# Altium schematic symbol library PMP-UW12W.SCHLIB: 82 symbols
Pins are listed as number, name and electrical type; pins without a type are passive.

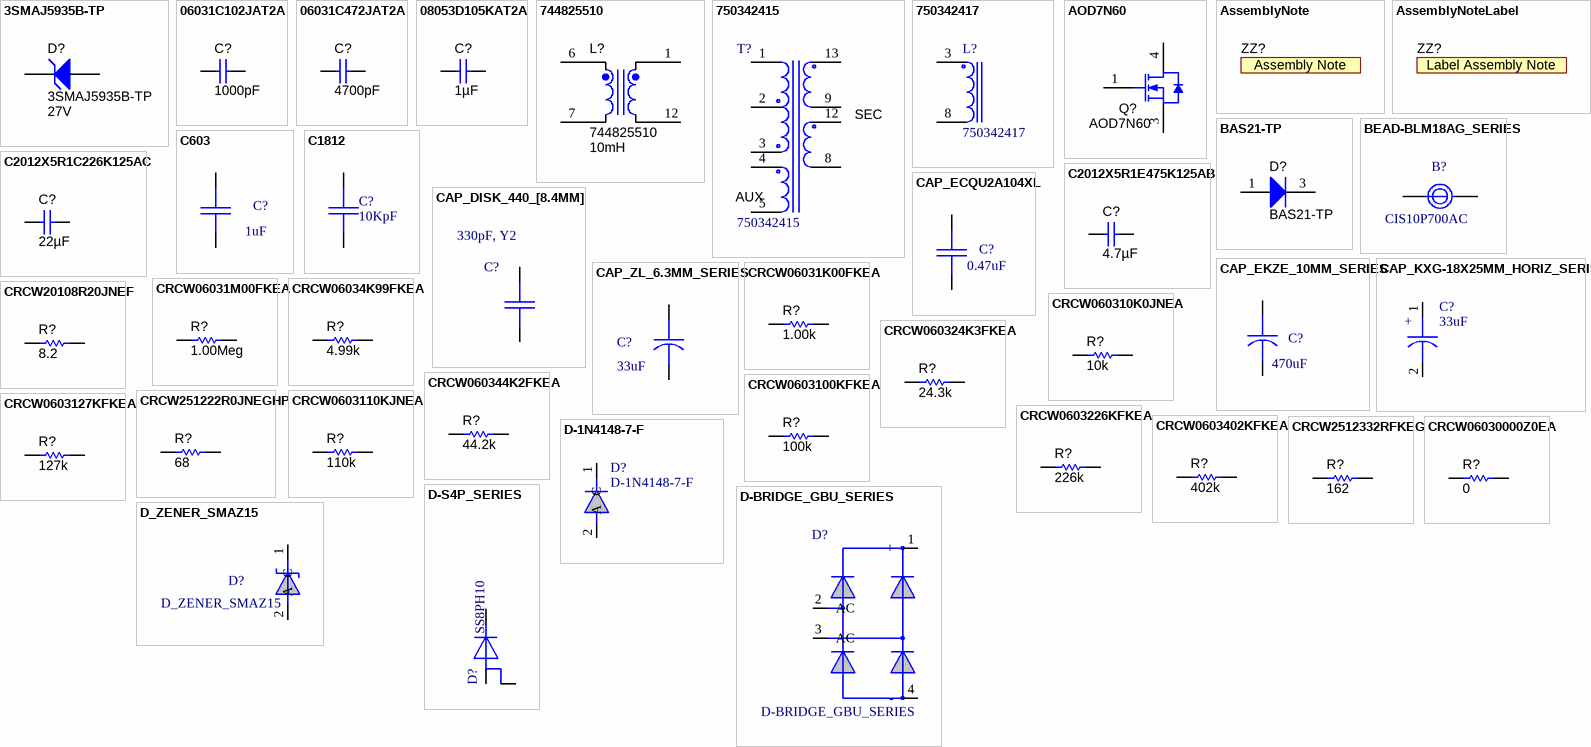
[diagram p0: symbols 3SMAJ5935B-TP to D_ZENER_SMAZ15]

## 3SMAJ5935B-TP
designator D?  value 27V
Diode, Zener, 27V, 3W, SMA; Manufacturer: Micro Commercial Components; SymbolCreator: a0412235; U/M: EA; Power_W: 3; Vz_V: 27; RJA_CperW: 226
signal-integrity model Diode
footprint SMA
pins: 1 K, 2 A

## 06031C102JAT2A
designator C?  ValueDisplayed: 1000pF  (hidden comment: 06031C102JAT2A)
CAP, CERM, 1000pF, 100V, +/-5%, X7R, 0603; Manufacturer: AVX; Polarized: N; CompType: Capacitor; U/M: EA; Cap_F: 0.000000001; Tolerance_%: 5; ESR_Ohm: 0.276; Value1: 0.276 ohm; VDC_V: 100; TaMin_C: -55; TaMax_C: 125; Cap_Case: 0603
signal-integrity model Cap
simulation model Cap
footprint 0603
footprint 0603M
footprint 0603L
footprint 0603_HV
footprint 0603S
pins: 1, 2

## 06031C472JAT2A
designator C?  ValueDisplayed: 4700pF  (hidden comment: 06031C472JAT2A)
CAP, CERM, 4700pF, 100V, +/-5%, X7R, 0603; Manufacturer: AVX; Polarized: N; CompType: Capacitor; U/M: EA; Cap_F: 0.0000000047; Tolerance_%: 5; ESR_Ohm: 0.136; Value1: 0.136 ohm; VDC_V: 100; TaMin_C: -55; TaMax_C: 125; Cap_Case: 0603
signal-integrity model Cap
simulation model Cap
footprint 0603
footprint 0603M
footprint 0603L
footprint 0603_HV
footprint 0603S
pins: 1, 2

## 08053D105KAT2A
designator C?  ValueDisplayed: 1µF  (hidden comment: 08053D105KAT2A)
CAP, CERM, 1uF, 25V, +/-10%, X5R, 0805; Manufacturer: AVX; Polarized: N; CompType: Capacitor; U/M: EA; Cap_F: 0.000001; Tolerance_%: 10; ESR_Ohm: 0.012; Value1: 0.012 ohm; VDC_V: 25; TaMin_C: -55; TaMax_C: 85; Cap_Case: 0805
signal-integrity model Cap
simulation model Cap
footprint 0805_HV
footprint 0805
footprint 0805M
footprint 0805L
pins: 1, 2

## 744825510
designator L?  ValueDisplayed: 10mH
Coupled inductor, 10mH, 5A, 0.055 ohm, TH; Manufacturer: Wurth Elektronik eiSos; SymbolCreator: a0799628; Ind_H: 10.0E-3; DCR_ohm: 0.055; Isat: 5
footprint WE-CMB_XL
pins: 1, 6, 7, 12

## 750342415
designator T?
TRANSFOERMER, 856uH, +/-10%, TH, 14-PIN; Manufacturer: WURTH ELEKTRONIK; CompType: TRANSFORMER; SymbolCreator: x0199378
footprint WE_750342415 (TRANSFOERMER, TH)
pins: 1, 2, 3, 4, 5, 8, 9, 12, 13

## 750342417
designator L?
TRANSFOERMER, 300uH, +/-10%, TH, 10-PIN; Manufacturer: WURTH ELEKTRONIK; CompType: TRANSFORMER; SymbolCreator: x0199378
footprint WE_750342417 (TRANSFOERMER, TH)
pins: 3, 8

## AOD7N60
designator Q?
MOSFET, N-CH, 600V, 7A, DPAK; Manufacturer: AOS; Alternate Manufacturer: None; U/M: EA; ChType: N; VdsMax_V: 600; Value1: ? ohm; Value2: 19.3 nC; QgTyp_nC: 19.3; Vgs_V: 30; IdsMax_A: 7
footprint DPAK
pins: 1 G, 3 S, 4 D

## AssemblyNote
designator ZZ?  (no BOM)
These assemblies are ESD sensitive, ESD precautions shall be observed.; Part_Number: Part Number; SymbolCreator: codlsc; CompType: AssemblyNote
footprint AssemblyNote

## AssemblyNoteLabel
designator ZZ?  (no BOM)
This Assembly Note is for PCB labels only; Part_Number: Part Number; SymbolCreator: a0412235
footprint AssemblyNoteLabel

## BAS21-TP
designator D?
Diode, P-N, 200V, 200A, SOT-23; Manufacturer: Micro Commercial Components; U/M: EA; Vf_V: 1.25; Value2: 1.25V; Io_A: 200; TJmax_C: 150; RJC_CperW: 430
signal-integrity model Model Name (Model Description)
footprint SOT-23
footprint SOT-23M
footprint SOT-23L
pins: 1 A, 3 K

## BEAD-BLM18AG_SERIES
designator B?, comment CIS10P700AC
FERRITE CHIP 70 OHM 4000MA 0603; Manufacturer: Samsung; Second Source: C:\program files\p-cad 2004\pcad_pdf's\Bead BML SERIES.pdf; Reference: \\vette02\pmp_pcb\pcad_pdf's\Bead BML SERIES.pdf; Area: 5.87 mm; Value: 70ohm; PCB DECAL: 0603
footprint xxxx (Footprint not found)
footprint 0603 (0603 from SM-752 data)
pins: 1, 2

## C603
designator C?  value 1uF  (hidden comment: C603)
CAP CER 1UF 25V 10% X7R 0603; Manufacturer: Kemet; PartNumber: C0603C105K3RACTU; Area: 5650
footprint C603
pins: 1, 2

## C1812
designator C?, comment value 10KpF  (hidden comment: C4532CH2J103K160KA)
Corporation CAP CER 10000PF 630V 10% CH 1812; Manufacturer: TDK Corporation; Area: 43,360
footprint C1812
pins: 1, 2
1 alternate drawing of the same symbol

## C2012X5R1C226K125AC
designator C?  ValueDisplayed: 22µF  (hidden comment: C2012X5R1C226K125AC)
CAP, CERM, 22uF, 16V, +/-10%, X5R, 0805; Manufacturer: TDK; Polarized: N; CompType: Capacitor; U/M: EA; Cap_F: 0.000022; Tolerance_%: 10; Value1: Unknown; VDC_V: 16; TaMin_C: -55; TaMax_C: 85; Cap_Case: 0805
signal-integrity model Cap
simulation model Cap
footprint 0805_HV
footprint 0805
footprint 0805M
footprint 0805L
pins: 1, 2

## C2012X5R1E475K125AB
designator C?  ValueDisplayed: 4.7µF  (hidden comment: C2012X5R1E475K125AB)
CAP, CERM, 4.7uF, 25V, +/-10%, X5R, 0805; Manufacturer: TDK; Polarized: N; CompType: Capacitor; U/M: EA; Cap_F: 0.0000047; Tolerance_%: 10; Value1: Unknown; VDC_V: 25; TaMin_C: -55; TaMax_C: 85; Cap_Case: 0805
signal-integrity model Cap
simulation model Cap
footprint 0805_HV
footprint 0805
footprint 0805M
footprint 0805L
pins: 1, 2

## CAP_DISK_440_[8.4MM]
designator C?  value 330pF, Y2  (hidden comment: CAP_DISK_440_[8.4MM])
CAP CER 330PF 300VAC 10% RADIAL; Manufacturer: Vishay; Part_Number: VY2331K29Y5SS63V7; PartNumber: Part Number; Description: Capacitor, 300VAC, X1Y2, ±10%; Area: 103.50 mm; Reference: \\vette02\pmp_pcb\pcad_pdf's\440l.pdf; Second_Source: C:\program files\p-cad 2004\pcad_pdf's\ABB0000CE12.pdf; Type: CAP_DISK_720; PCB DECAL: CAP_DISK_8.4MM; Second Source: C:\program files\p-cad2004pcad_pdf's\440l.pdf
footprint CAP_DISK_8.4MM
pins: 1, 2

## CAP_ECQU2A104XL
designator C?, comment value 0.47uF  (hidden comment: R46KI347050P1M)
CAP FILM 0.47UF 560VDC RADIAL; Manufacturer: Kemet; PCB DECAL: 18.00mm x 9.00mm; Area: 97500
footprint CAP_591MIL
pins: 1, 2

## CAP_EKZE_10MM_SERIES
designator C?  value 470uF  (hidden comment: CAP_EKZE_10MM_SERIES)
CAP ALUM 470UF 35V 20% RADIAL; Manufacturer: Panasonic; Part_Number: EEU-FM1V471; Part_Number: Part Number; Area: 96.42 mm; PCB DECAL: CAP_ALUM-10MM; Second Source: C:\program files\p-cad 2004\pcad_pdf's\ekze_cap.pdf; Reference: \\vette02\pmp_pcb\pcad_pdf's\ekze_cap.pdf
footprint CAP_ALUM-10MM
pins: 1, 2

## CAP_KXG-18X25MM_HORIZ_SERIES
designator C?, comment 33uF
Capacitor, Electrolytic, -40 to +105 °C; PartNumber: EKXG451ELL330MM20S; Manufacturer: Nippon; Area: 667.40 mm; Value: xx uH
footprint CAP_EEUFC1H
pins: 1, 2
1 alternate drawing of the same symbol

## CAP_ZL_6.3MM_SERIES
designator C?  value 33uF  (hidden comment: CAP_ZL_6.3MM_SERIES)
CAP ALUM 33UF 35V 20% RADIAL; Manufacturer: Rubycon; Part_Number: 35YXJ33M5X11; PartNumber: Part Number; Area: 70,686; Type: CAP_ZL_6.3MM SERIES; PCB DECAL: CAP_ZL-6.3MM
footprint CAP_ZL-6.3MM
pins: 1, 2

## CRCW06031K00FKEA
designator R?  value 1.00k  (hidden comment: CRCW06031K00FKEA)
RES, 1.00k ohm, 1%, 0.1W, 0603; Manufacturer: Vishay-Dale; CompType: Resistor; Res_ohm: 1000; Value_Code: 1k00; Tolerance_%: 1; Power_W: 0.1; VDC_V: 75; TempCo: 100 ppm/C; EIA_Code: E96; U/M: EA
signal-integrity model Resistor
simulation model Resistor
footprint 0603
footprint 0603M
footprint 0603L
footprint 0603_HV
footprint 0603S
pins: 1, 2

## CRCW06031M00FKEA
designator R?  value 1.00Meg  (hidden comment: CRCW06031M00FKEA)
RES, 1.00Meg ohm, 1%, 0.1W, 0603; Manufacturer: Vishay-Dale; CompType: Resistor; Res_ohm: 1000000; Value_Code: 1M00; Tolerance_%: 1; Power_W: 0.1; VDC_V: 75; TempCo: 100 ppm/C; EIA_Code: E96; U/M: EA
signal-integrity model Resistor
simulation model Resistor
footprint 0603
footprint 0603M
footprint 0603L
footprint 0603_HV
footprint 0603S
pins: 1, 2

## CRCW06034K99FKEA
designator R?  value 4.99k  (hidden comment: CRCW06034K99FKEA)
RES, 4.99k ohm, 1%, 0.1W, 0603; Manufacturer: Vishay-Dale; CompType: Resistor; Res_ohm: 4990; Value_Code: 4k99; Tolerance_%: 1; Power_W: 0.1; VDC_V: 75; TempCo: 100 ppm/C; EIA_Code: E96; U/M: EA
signal-integrity model Resistor
simulation model Resistor
footprint 0603
footprint 0603M
footprint 0603L
footprint 0603_HV
footprint 0603S
pins: 1, 2

## CRCW20108R20JNEF
designator R?  value 8.2  (hidden comment: CRCW20108R20JNEF)
RES, 8.2 ohm, 5%, 0.75W, 2010; Manufacturer: Vishay-Dale; CompType: Resistor; Value_Code: 8R20; Tolerance_%: 5; Power_W: 0.75; VDC_V: 400; TempCo: 200 ppm/C; EIA_Code: E24; U/M: EA
signal-integrity model Resistor
simulation model Resistor
footprint 2010M
footprint 2010L
footprint 2010
pins: 1, 2

## CRCW060310K0JNEA
designator R?  value 10k  (hidden comment: CRCW060310K0JNEA)
RES, 10k ohm, 5%, 0.1W, 0603; Manufacturer: Vishay-Dale; CompType: Resistor; Res_ohm: 10000; Value_Code: 10k0; Tolerance_%: 5; Power_W: 0.1; VDC_V: 75; TempCo: 200 ppm/C; EIA_Code: E24; U/M: EA
signal-integrity model Resistor
simulation model Resistor
footprint 0603
footprint 0603M
footprint 0603L
footprint 0603_HV
footprint 0603S
pins: 1, 2

## CRCW060324K3FKEA
designator R?  value 24.3k  (hidden comment: CRCW060324K3FKEA)
RES, 24.3k ohm, 1%, 0.1W, 0603; Manufacturer: Vishay-Dale; CompType: Resistor; Res_ohm: 24300; Value_Code: 24k3; Tolerance_%: 1; Power_W: 0.1; VDC_V: 75; TempCo: 100 ppm/C; EIA_Code: E96; U/M: EA
signal-integrity model Resistor
simulation model Resistor
footprint 0603
footprint 0603M
footprint 0603L
footprint 0603_HV
footprint 0603S
pins: 1, 2

## CRCW060344K2FKEA
designator R?  value 44.2k  (hidden comment: CRCW060344K2FKEA)
RES, 44.2k ohm, 1%, 0.1W, 0603; Manufacturer: Vishay-Dale; CompType: Resistor; Res_ohm: 44200; Value_Code: 44k2; Tolerance_%: 1; Power_W: 0.1; VDC_V: 75; TempCo: 100 ppm/C; EIA_Code: E96; U/M: EA
signal-integrity model Resistor
simulation model Resistor
footprint 0603
footprint 0603M
footprint 0603L
footprint 0603_HV
footprint 0603S
pins: 1, 2

## CRCW251222R0JNEGHP
designator R?, comment value 68  (hidden comment: RHC2512FT68R0)
RES 68 OHM 2W 1% 2512; Manufacturer: Stackpole Electronics Inc; CompType: Resistor; Tolerance_%: 1
signal-integrity model Resistor
simulation model Resistor
footprint 2512M
footprint 2512L
footprint 2512
pins: 1, 2

## CRCW0603100KFKEA
designator R?  value 100k  (hidden comment: CRCW0603100KFKEA)
RES, 100k ohm, 1%, 0.1W, 0603; Manufacturer: Vishay-Dale; CompType: Resistor; Res_ohm: 100000; Tolerance_%: 1; Power_W: 0.1; VDC_V: 75; TempCo: 100 ppm/C; EIA_Code: E96; U/M: EA
signal-integrity model Resistor
simulation model Resistor
footprint 0603
footprint 0603M
footprint 0603L
footprint 0603_HV
footprint 0603S
pins: 1, 2

## CRCW0603110KJNEA
designator R?  value 110k  (hidden comment: CRCW0603110KJNEA)
RES, 110k ohm, 5%, 0.1W, 0603; Manufacturer: Vishay-Dale; CompType: Resistor; Res_ohm: 110000; Tolerance_%: 5; Power_W: 0.1; VDC_V: 75; TempCo: 200 ppm/C; EIA_Code: E24; U/M: EA
signal-integrity model Resistor
simulation model Resistor
footprint 0603
footprint 0603M
footprint 0603L
footprint 0603_HV
footprint 0603S
pins: 1, 2

## CRCW0603127KFKEA
designator R?  value 127k  (hidden comment: CRCW0603127KFKEA)
RES, 127k ohm, 1%, 0.1W, 0603; Manufacturer: Vishay-Dale; CompType: Resistor; Res_ohm: 127000; Tolerance_%: 1; Power_W: 0.1; VDC_V: 75; TempCo: 100 ppm/C; EIA_Code: E96; U/M: EA
signal-integrity model Resistor
simulation model Resistor
footprint 0603
footprint 0603M
footprint 0603L
footprint 0603_HV
footprint 0603S
pins: 1, 2

## CRCW0603226KFKEA
designator R?  value 226k  (hidden comment: CRCW0603226KFKEA)
RES, 226k ohm, 1%, 0.1W, 0603; Manufacturer: Vishay-Dale; CompType: Resistor; Res_ohm: 226000; Tolerance_%: 1; Power_W: 0.1; VDC_V: 75; TempCo: 100 ppm/C; EIA_Code: E96; U/M: EA
signal-integrity model Resistor
simulation model Resistor
footprint 0603
footprint 0603M
footprint 0603L
footprint 0603_HV
footprint 0603S
pins: 1, 2

## CRCW0603402KFKEA
designator R?  value 402k  (hidden comment: CRCW0603402KFKEA)
RES, 402k ohm, 1%, 0.1W, 0603; Manufacturer: Vishay-Dale; CompType: Resistor; Res_ohm: 402000; Tolerance_%: 1; Power_W: 0.1; VDC_V: 75; TempCo: 100 ppm/C; EIA_Code: E96; U/M: EA
signal-integrity model Resistor
simulation model Resistor
footprint 0603
footprint 0603M
footprint 0603L
footprint 0603_HV
footprint 0603S
pins: 1, 2

## CRCW2512332RFKEG
designator R?, comment value 162  (hidden comment: CRCW2512162RFKEGHP)
RES 162 OHM 1.5W 1% 2512 SMD; Manufacturer: Vishay-Dale; CompType: Resistor; Value_Code: 162R; Tolerance_%: 1; EIA_Code: E96; U/M: EA
signal-integrity model Resistor
simulation model Resistor
footprint 2512M
footprint 2512L
footprint 2512
pins: 1, 2

## CRCW06030000Z0EA
designator R?  value 0  (hidden comment: CRCW06030000Z0EA)
RES, 0 ohm, 5%, 0.1W, 0603; Manufacturer: Vishay-Dale; CompType: Resistor; Value_Code: 0000; Tolerance_%: 5; Power_W: 0.1; VDC_V: 75; TempCo: 200 ppm/C; EIA_Code: E24; U/M: EA
signal-integrity model Resistor
simulation model Resistor
footprint 0603
footprint 0603M
footprint 0603L
footprint 0603_HV
footprint 0603S
pins: 1, 2

## D-1N4148-7-F
designator D?
Diode, Signal, 300-mA, 75-V, 350-mW; PartNumber: 1N4148W-7-F; Manufacturer: Diodes; Area: 13300; Value: 1N4148W-7-F
footprint D_SOD123
pins: 1 C, 2 A

## D-BRIDGE_GBU_SERIES
designator D?
Diode, Bridge Rectifier, 8 A, xxxV; PartNumber: GBUxx; Manufacturer: Fairchild; Area: 163800; Value: GBUxx
footprint BRIDGE-INLINE-210-C
pins: 1 +, 2 AC, 3 AC, 4 -

## D-S4P_SERIES
designator D?  value SS8PH10  (hidden comment: D-S4P_SERIES)
Diode Schottky, 8A, 100V; PartNumber: SS8PH10-M3/86A; Manufacturer: Vishay; Area: 73600; PCB DECAL: TO-277[SMPC]; Second Source: C:\program files\p-cad 2004\pcad_pdf's\s4pm[1].pdf; Reference: \\vette02\pmp_pcb\pcad_pdf's\s4pm[1].pdf
footprint TO-277[SMPC]
pins: 1, 2 A, 3 C

## D_ZENER_SMAZ15
designator D?
Diode, Zener,15-V, 1W; PartNumber: SMAZ15; Manufacturer: Diodes; Area: 37520; Value: SMAZ15
footprint DIODE_SMA
pins: 1 C, 2 A

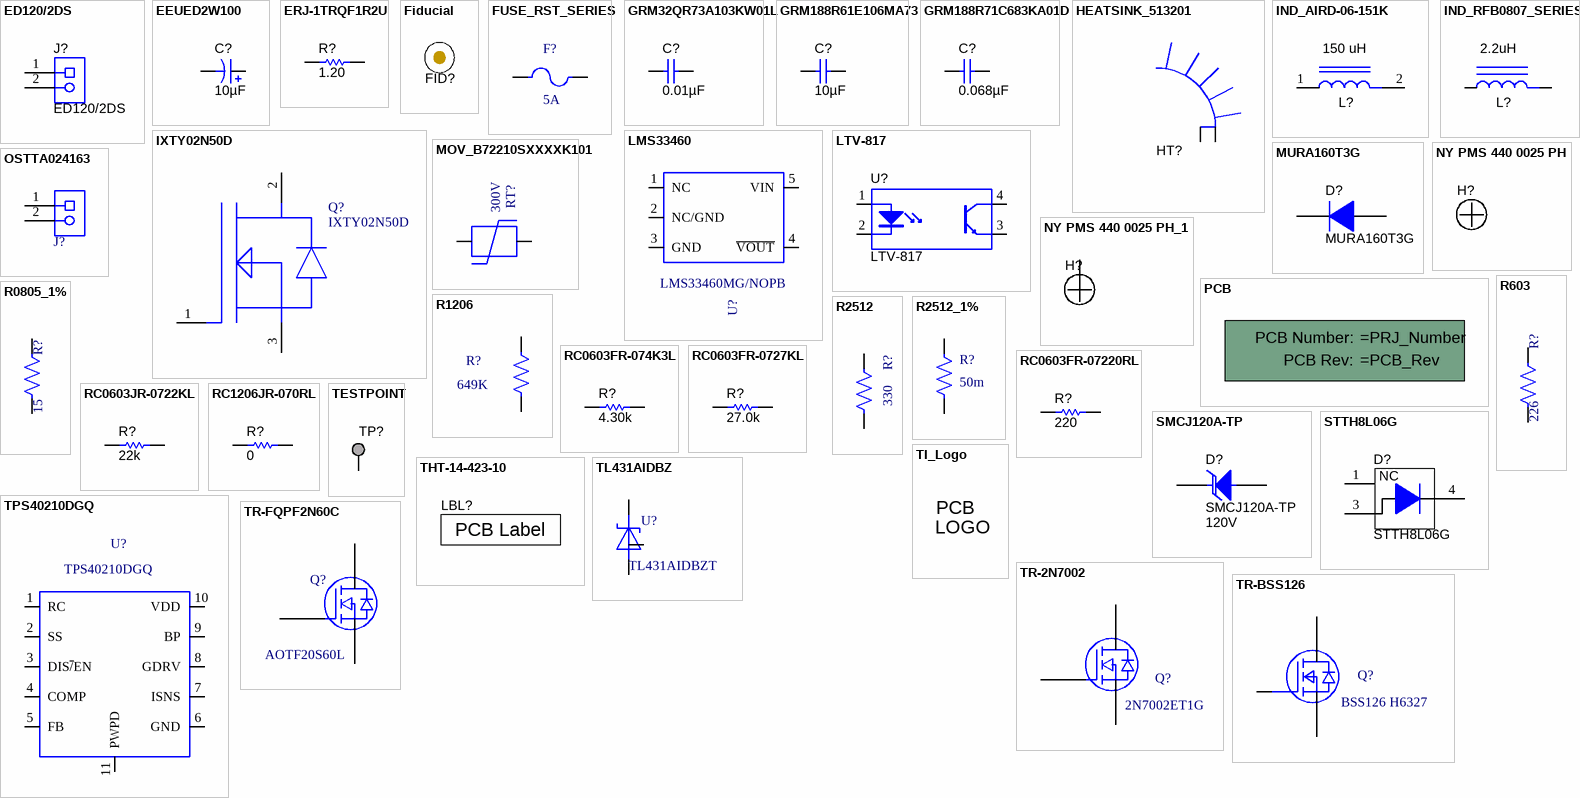
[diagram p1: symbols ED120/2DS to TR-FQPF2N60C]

## ED120/2DS
designator J?
TERMINAL BLOCK 5.08MM VERT 2POS, TH; Manufacturer: On-Shore Technology; SymbolCreator: a0412235; U/M: EA
footprint CONN_ED120-2DS
pins: 1, 2

## EEUED2W100
designator C?  ValueDisplayed: 10µF  (hidden comment: EEUED2W100)
CAP, AL, 10uF, 450V, +/-20%, 2.864788 ohm, TH; Manufacturer: Panasonic; Polarized: Y; CompType: Capacitor; U/M: EA; Cap_F: 0.00001; Tolerance_%: 20; VDC_V: 450; IRMS_A: 0.35; TaMin_C: -25; TaMax_C: 105; AC_Derating: 0.3
signal-integrity model Cap
simulation model Cap
footprint CAPPR5-12.5X20
footprint CAPPR5-12.5X20_HorizontalUp
footprint CAPPR5-12.5X20_HorizontalDown
pins: 1 +, 2 -

## ERJ-1TRQF1R2U
designator R?  value 1.20  (hidden comment: ERJ-1TRQF1R2U)
RES, 1.20 ohm, 1%, 1W, 2512; Manufacturer: Panasonic; CompType: Resistor; Res_ohm: 1.2; Value_Code: 1R20; Tolerance_%: 1; TempCo: 100 ppm/C; U/M: EA
signal-integrity model Resistor
simulation model Resistor
footprint 2512M
footprint 2512L
footprint 2512
pins: 1, 2

## Fiducial
designator FID?  (value not drawn)
Fiducial mark.  There is nothing to buy or mount.; Part_Number: Part Number; SymbolCreator: codlsc
footprint Fiducial10-30
footprint Fiducial10-20
footprint Fiducial15-30
footprint Fiducial20-40
footprint Fiducial6.4-20
footprint Fiducial10-30_Panel

## FUSE_RST_SERIES
designator F?  value 5A  (hidden comment: FUSE_RST_SERIES)
FUSE SLOW 250VAC 5A RADIAL; Manufacturer: BEL; PartNumber: RST 5; Area: 43.2 mm; PCB DECAL: FUSE_4X8.5-5.08P; Reference: \\vette02\pmp_pcb\pcad_pdf's\RST.pdf; Second Source: C:\program files\p-cad 2004\pcad_pdf's\RST.pdf
footprint FUSE_4X8.5-5.08P
pins: 1, 2

## GRM32QR73A103KW01L
designator C?  ValueDisplayed: 0.01µF  (hidden comment: GRM32QR73A103KW01L)
CAP, CERM, 0.01uF, 1000V, +/-10%, X7R, 1210; Manufacturer: MuRata; Polarized: N; CompType: Capacitor; U/M: EA; Cap_F: 0.00000001; Tolerance_%: 10; Value1: Unknown; VDC_V: 1000; TaMin_C: -55; TaMax_C: 125; Cap_Case: 1210
signal-integrity model Cap
simulation model Cap
footprint 1210
footprint 1210M
footprint 1210L
pins: 1, 2

## GRM188R61E106MA73
designator C?  ValueDisplayed: 10µF  (hidden comment: GRM188R61E106MA73)
CAP, CERM, 10uF, 25V, +/-20%, X5R, 0603; Manufacturer: MuRata; Polarized: N; CompType: Capacitor; U/M: EA; Cap_F: 0.00001; Tolerance_%: 20; Value1: Unknown; VDC_V: 25; TaMin_C: -55; TaMax_C: 85; Cap_Case: 0603
signal-integrity model Cap
simulation model Cap
footprint 0603
footprint 0603M
footprint 0603L
footprint 0603_HV
footprint 0603S
pins: 1, 2

## GRM188R71C683KA01D
designator C?  ValueDisplayed: 0.068µF  (hidden comment: GRM188R71C683KA01D)
CAP, CERM, 0.068uF, 16V, +/-10%, X7R, 0603; Manufacturer: MuRata; Polarized: N; CompType: Capacitor; U/M: EA; Cap_F: 0.000000068; Tolerance_%: 10; Value1: Unknown; VDC_V: 16; TaMin_C: -55; TaMax_C: 125; Cap_Case: 0603
signal-integrity model Cap
simulation model Cap
footprint 0603
footprint 0603M
footprint 0603L
footprint 0603_HV
footprint 0603S
pins: 1, 2

## HEATSINK_513201
designator HT?, comment HEATSINK_513102B02500G  (value not drawn)
HEATSINK TO-220 W/PINS 1.5"TALL; Manufacturer: Aavid Thermalloy; area: 739800
footprint HEATSINK_513201
pins: 1, 2

## IND_AIRD-06-151K
designator L?, comment 150 uH
INDUCTOR 150UH 4.0A 10%; Manufacturer: Abracon Corporation; Part Number: AIRD-06-151K; Area: 113411; sp: AIRD-06-151K-ND; sup: Digi-Key
footprint IND_AIRD-06-151K
pins: 1, 2

## IND_RFB0807_SERIES
designator L?, comment 2.2uH
INDUCTOR 2.2UH 4.1A RADIAL; Manufacturer: Taiyo Yuden; Part_Number: LHL08TB2R2M; Area: 113411; Type: PD2 744; PCB DECAL: IND_200_MIL
footprint IND_200_MIL
pins: 1, 2

## IXTY02N50D
designator Q?
DISCRETE, MOSFET N-CH 500V 200MA, DPAK; Manufacturer: IXYS; SymbolCreator: x0199378
footprint TO228P991X238-3N
pins: 1 G, 2 D, 3 S

## LMS33460
designator U?  value LMS33460MG/NOPB  (hidden comment: LMS33460)
IC DETECTOR UNDER VOLT 3V SC70-5; Manufacturer: TI; Second Source: C:\program files\p-cad 2004\pcad_pdf's\lms33460[1].pdf; Reference: \\vette02\pmp_pcb\pcad_pdf's\lms33460[1].pdf; Area: 12.05 mm; PCB DECAL: SC-70-5
footprint SC-70-5
pins: 1 NC, 2 NC/GND, 3 GND, 4 ~{VOUT}, 5 VIN

## LTV-817
designator U?
Opto-Isolator, 1 Channel, TH; Manufacturer: Lite-On; CompType: OPTOCOUPLER; U/M: EA
footprint DIP762W60P254L460H350Q4B
pins: 1 A, 2 K, 3 E, 4 C

## MOV_B72210SXXXXK101
designator RT?  value 300V  (hidden comment: MOV_B72210SXXXXK101)
MOV, 300V; Manufacturer: Bourns; Part_Number: MOV-10D471KTR; Area: 85,500; PCB DECAL: DISK-472
footprint DISK-472
pins: 1, 2

## MURA160T3G
designator D?
Diode, Ultrafast, 600V, 1A, SMA; Manufacturer: ON Semiconductor; U/M: EA; Vf_V: 1.05; Value2: 1.05V; Io_A: 1; Vr_V: 600; TJmax_C: 175
signal-integrity model Diode
simulation model Dmura160t3
footprint SMA
pins: 1 K, 2 A

## NY PMS 440 0025 PH
designator H?
Mounting Hole M3 3.5mm; Manufacturer: STD; CompType: Hardware; U/M: EA
footprint MH3.2_H5_W6_KO8_STARHEAD

## NY PMS 440 0025 PH_1
designator H?
Mounting Hole M3 3.5mm; Manufacturer: STD; CompType: Hardware; U/M: EA
footprint NY PMS 440 0025 PH (4-40 nylon screw and mounting hole)
footprint NY PMS 440 0025 PH (4-40 nylon screw and mounting hole)
pins: 1

## OSTTA024163
designator J?  (value not drawn)
Terminal Block, 2x1, 5.08mm, TH; PartNumber: OSTTC022162; Manufacturer: On-Shore Technology; SymbolCreator: a0412235; U/M: EA
footprint On-Shore_OSTTA024163
pins: 1, 2

## PCB
designator !PCB?  (mechanical)
Printed Circuit Board; Manufacturer: Any; Part_Number: Part Number; SymbolCreator: a0412235; CompType: PCB
1 alternate drawing of the same symbol

## R603
designator R?  value 226  (hidden comment: R603)
RES 226 OHM 1/10W 1% 0603 SMD; Part_Number: RC0603FR-07226RL; Manufacturer: Yageo; Area: 5650
footprint R603
pins: 1, 2

## R0805_1%
designator R?  value 15  (hidden comment: R0805_1%)
RES 15.0 OHM 1/8W 1% 0805 SMD; Part_Number: RC0805FR-0715RL; Manufacturer: Yageo; Area: 15,300; PCB DECAL: R0805
footprint R0805
pins: 1, 2

## R1206
designator R?  value 649K  (hidden comment: R1206)
RES 649K OHM 1/4W 1% 1206 SMD; Manufacturer: Yageo; PartNumber: RC1206FR-07649KL; Area: 15390
footprint r1206
pins: 1, 2

## R2512
designator R?  value 330  (hidden comment: R2512)
RES 330 OHM 1W 5% 2512; Manufacturer: Samsung; PartNumber: RC6432J331CS; Area: 35100
footprint R2512
pins: 1, 2

## R2512_1%
designator R?  value 50m  (hidden comment: R2512_1%)
RES 0.05 OHM 1W 1% 2512 SMD; Part_Number: LRMAM2512-R05FT4; Manufacturer: TT/Welwyn; PartNumber: LRMAM2512-R02FT4; Area: 56000; PCB DECAL: R2512; Second Source: C:\program files\p-cad 2004\pcad_pdf's\SML-LXR1206USBC-TR[1].pdf; Reference: \\vette02\pmp_pcb\pcad_pdf's\SML-LXR1206USBC-TR[1].pdf
footprint R2512
pins: 1, 2

## RC0603FR-074K3L
designator R?  value 4.30k  (hidden comment: RC0603FR-074K3L)
RES, 4.30k ohm, 1%, 0.1W, 0603; Manufacturer: Yageo America; CompType: Resistor; Res_ohm: 4300; Value_Code: 4k30; Tolerance_%: 1; Power_W: 0.1; VDC_V: 150; TempCo: 200 ppm/C; U/M: EA
signal-integrity model Resistor
simulation model Resistor
footprint 0603
footprint 0603M
footprint 0603L
footprint 0603_HV
footprint 0603S
pins: 1, 2

## RC0603FR-0727KL
designator R?  value 27.0k  (hidden comment: RC0603FR-0727KL)
RES, 27.0k ohm, 1%, 0.1W, 0603; Manufacturer: Yageo America; CompType: Resistor; Res_ohm: 27000; Value_Code: 27k0; Tolerance_%: 1; Power_W: 0.1; VDC_V: 150; TempCo: 200 ppm/C; U/M: EA
signal-integrity model Resistor
simulation model Resistor
footprint 0603
footprint 0603M
footprint 0603L
footprint 0603_HV
footprint 0603S
pins: 1, 2

## RC0603FR-07220RL
designator R?  value 220  (hidden comment: RC0603FR-07220RL)
RES, 220 ohm, 1%, 0.1W, 0603; Manufacturer: Yageo America; CompType: Resistor; Value_Code: 220R; Tolerance_%: 1; Power_W: 0.1; VDC_V: 150; TempCo: 200 ppm/C; U/M: EA
signal-integrity model Resistor
simulation model Resistor
footprint 0603
footprint 0603M
footprint 0603L
footprint 0603_HV
footprint 0603S
pins: 1, 2

## RC0603JR-0722KL
designator R?  value 22k  (hidden comment: RC0603JR-0722KL)
RES, 22k ohm, 5%, 0.1W, 0603; Manufacturer: Yageo America; CompType: Resistor; Res_ohm: 22000; Value_Code: 22k0; Tolerance_%: 5; Power_W: 0.1; VDC_V: 50; TempCo: 100 ppm/C; EIA_Code: E24; U/M: EA
signal-integrity model Resistor
simulation model Resistor
footprint 0603
footprint 0603M
footprint 0603L
footprint 0603_HV
footprint 0603S
pins: 1, 2

## RC1206JR-070RL
designator R?  value 0  (hidden comment: RC1206JR-070RL)
RES, 0 ohm, 5%, 0.25W, 1206; Manufacturer: Yageo America; CompType: Resistor; Value_Code: 0000; Tolerance_%: 5; Power_W: 0.25; VDC_V: 200; TempCo: 200 ppm/C; EIA_Code: E24; U/M: EA
signal-integrity model Resistor
simulation model Resistor
footprint 1206
footprint 1206M
footprint 1206L
pins: 1, 2

## SMCJ120A-TP
designator D?  value 120V
Diode, TVS, Uni, 120V, 1500W, SMC; Manufacturer: Micro Commercial Components; U/M: EA; Power_W: 1500; Vr_V: 120
footprint SMC
pins: 1 K, 2 A

## STTH8L06G
designator D?
Diode, Ultrafast, 600V, 8A, DDPAK; Manufacturer: ST Microelectronics; SymbolCreator: a0412235; U/M: EA; Vf_V: 0.0875; Value2: 0.0875V; Io_A: 8; Vr_V: 600; TJmax_C: 175; RJC_CperW: 2.5
signal-integrity model Diode
footprint DDPAK
pins: 1 NC, 3 A, 4 K

## TESTPOINT
designator TP?  (value not drawn)  (no BOM)
TEST POINT.  No entry in BOM.; PartNumber: Part Number
footprint TESTPOINT
footprint TP_VIA_018RND008
pins: 1

## THT-14-423-10
designator LBL?
Thermal Transfer Printable Labels, 0.650" W x 0.200" H - 10,000 per roll; Manufacturer: Brady; PartNumber: THT-14-423-10; Part_Number: Part Number; SymbolCreator: a0412235; CompType: Label; Note: Size: 0.65" x 0.20 "
footprint Label_650x200

## TI_Logo
designator Logo?  (no BOM)
Texas Instrument Corporate Signature; Part_Number: Part Number; SymbolCreator: codlsc
footprint TI_Stacked_SolderMask_Medium
footprint TI_Stacked_SolderMask_Small
footprint TI_Stacked_Overlay_Medium
footprint TI_Stacked_Overlay_Small
footprint TI_Horizontal_SolderMask_Medium
footprint TI_Horizontal_SolderMask_Small
footprint TI_Horizontal_Overlay_Medium
footprint TI_Horizontal_Overlay_Small
footprint TI_Symbol_SolderMask_Small
footprint TI_Symbol_Overlay_Medium
footprint TI_Symbol_Overlay_Small
footprint TI_Symbol_SolderMask_Medium

## TL431AIDBZ
designator U?  value TL431AIDBZT  (hidden comment: TL431AIDBZ)
IC VREF SHUNT PREC ADJ SOT23-3; Manufacturer: TI; Second Source: C:\program files\p-cad 2004\pcad_pdf's\TL431A-B.pdf; Reference: \\vette02\pmp_pcb\pcad_pdf's\TL431A-B.pdf; Area: 16384; PCB DECAL: SOT-23
footprint SOT-23 (SOT23, 3-Leads, Body 2.9x1.3mm, Pitch 0.95mm, Lead Span 2.5mm, IPC Medium Density)
pins: 1 C, 2 REF, 3 A

## TPS40210DGQ
designator U?
IC REG CTRLR BST FLYBK CM 10MSOP; Manufacturer: TI; PartNumber: TPS40210DGQR; Area: 38400; Reference: \\vette02\pmp_pcb\pcad_pdf's\tps40210.pdf; Second Source: C:\program files\p-cad 2004\pcad_pdf's\tps40210.pdf; PCB DECAL: DGQ_10PWP
footprint DGQ_10PWP
pins: 1 RC, 2 SS, 3 DIS~{/}EN, 4 COMP, 5 FB, 6 GND, 7 ISNS, 8 GDRV, 9 BP, 10 VDD, 11 PWPD

## TR-2N7002
designator Q?  value 2N7002ET1G  (hidden comment: TR-2N7002)
MOSFET N-CH 60V 260MA SOT-23; Manufacturer: OnSemi; Second Source: C:\program files\p-cad 2004\pcad_pdf's\Diodes_2n7002.pdf; Reference: \\vette02\pmp_pcb\pcad_pdf's\Diodes_2n7002.pdf; Area: 14105
footprint SOT-23 (SOT23, 3-Leads, Body 2.9x1.3mm, Pitch 0.95mm, Lead Span 2.5mm, IPC Medium Density)
pins: 1 G, 2 S, 3 D

## TR-BSS126
designator Q?  value BSS126 H6327  (hidden comment: TR-BSS126)
MOSFET N-CH 600V 21MA SOT23; Manufacturer: Infineon; Second Source: C:\program files\p-cad 2004\pcad_pdf's\BSS126.pdf; Reference: \\vette02\pmp_pcb\pcad_pdf's\BSS126.pdf; Area: 14105; PCB DECAL: SOT-23
footprint SOT-23 (SOT23, 3-Leads, Body 2.9x1.3mm, Pitch 0.95mm, Lead Span 2.5mm, IPC Medium Density)
pins: 1 G, 2 S, 3 D

## TR-FQPF2N60C
designator Q?  value AOTF20S60L  (hidden comment: TR-FQPF2N60C)
MOSFET, Nch, 600-V, 20A, 0.199 Ohms; Manufacturer: Alpha&Omega; Area: 65.4 mm; PCB DECAL: TO-220V; Reference: \\vette02\pmp_pcb\pcad_pdf's\FQPF2N60C.pdf; Second Source: C:\program files\p-cad 2004\pcad_pdf's\FQPF2N60C.pdf
footprint TO-220V
pins: 1 G, 2 D, 3 S

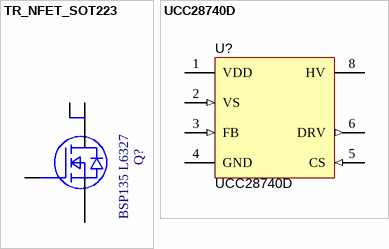
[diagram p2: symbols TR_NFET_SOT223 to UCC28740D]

## TR_NFET_SOT223
designator Q?  value BSP135 L6327  (hidden comment: TR_NFET_SOT223)
MOSFET N-CH 600V 120MA SOT-223; Manufacturer: Infineon; Second Source: C:\program files\p-cad 2004\pcad_pdf's\BSS126.pdf; Reference: \\vette02\pmp_pcb\pcad_pdf's\BSS126.pdf; Area: 86400; PCB DECAL: TR_SOT223
footprint TR_SOT223
pins: 1 G, 2 D, 3 S, 4 D

## UCC28740D
designator U?
Constant-Voltage, Constant-Current Flyback Controller Using Opto-Coupler Feedback, D0007A; Alternate Manufacturer: None; Manufacturer: Texas Instruments; SymbolCreator: a0412235; CompType: IC; U/M: EA
footprint D0007A_N
footprint D0007A_M
footprint D0007A_L
pins: 1 VDD (power), 2 VS (in), 3 FB (in), 4 GND (power), 5 CS (in), 6 DRV (out), 8 HV (power)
